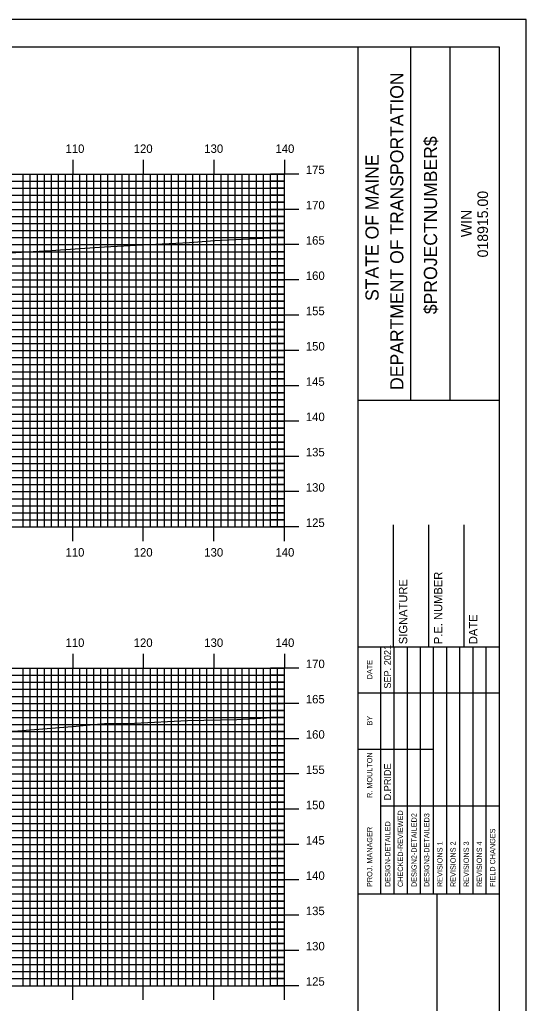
# Model space of a CAD drawing. Extents: x 1783041 to 1783384, y 442591 to 442811.
# Drawn here: x 1783309 to 1783380.7, y 442671.2 to 442810.5 of the extents above; entities that cross this region are included whole.
import ezdxf

# ---------------------------------------------------------------- set-up
doc = ezdxf.new("R2010")
doc.units = 0
for name, color, linetype in [('BORDER', 7, 'Continuous'), ('H_V ANNOTATION', 7, 'Continuous'), ('MAJOR', 7, 'Continuous'), ('MINOR', 7, 'Continuous'), ('PLOT BOUNDARY', 7, 'Continuous'), ('S_Roadway_Centerline', 7, 'Continuous')]:
    doc.layers.add(name, color=color, linetype=linetype)

msp = doc.modelspace()

# ---------------------------------------------------------------- linework, layer by layer
at = {"layer": 'BORDER'}
for p, q in [((1783356.86, 442596.67), (1783356.86, 442806.67)), ((1783364.32, 442756.66), (1783364.32, 442806.66)), ((1783369.91, 442756.66), (1783369.91, 442806.66)), ((1783356.86, 442756.65), (1783376.86, 442756.65)), ((1783356.86, 442756.65), (1783376.86, 442756.65)), ((1783361.86, 442721.67), (1783361.86, 442738.97)), ((1783361.86, 442721.67), (1783361.86, 442738.97)), ((1783366.86, 442721.67), (1783366.86, 442738.97)), ((1783366.86, 442721.67), (1783366.86, 442738.97)), ((1783371.86, 442721.67), (1783371.86, 442738.97)), ((1783371.86, 442721.67), (1783371.86, 442738.97)), ((1783356.86, 442721.67), (1783376.86, 442721.67)), ((1783356.86, 442721.67), (1783376.86, 442721.67)), ((1783356.86, 442686.67), (1783376.86, 442686.67)), ((1783356.86, 442686.67), (1783376.86, 442686.67)), ((1783368.04, 442616.67), (1783368.04, 442686.67)), ((1783368.04, 442616.67), (1783368.04, 442686.67))]:
    msp.add_line(p, q, dxfattribs=at)
msp.add_lwpolyline([(1783056.86, 442596.67), (1783376.86, 442596.67), (1783376.86, 442806.67), (1783056.86, 442806.67)], close=True, dxfattribs=at)
for points in [[(1783360.09, 442715.17), (1783360.09, 442721.67)], [(1783360.09, 442715.17), (1783360.09, 442721.67)], [(1783361.96, 442686.68), (1783361.96, 442721.67)], [(1783361.96, 442686.68), (1783361.96, 442721.67)], [(1783363.82, 442721.67), (1783363.82, 442686.68)], [(1783363.82, 442721.67), (1783363.82, 442686.68)], [(1783365.68, 442686.68), (1783365.68, 442721.67)], [(1783365.68, 442686.68), (1783365.68, 442721.67)], [(1783367.55, 442686.68), (1783367.55, 442721.67)], [(1783367.55, 442686.68), (1783367.55, 442721.67)], [(1783369.41, 442686.68), (1783369.41, 442721.67)], [(1783369.41, 442686.68), (1783369.41, 442721.67)], [(1783371.27, 442686.68), (1783371.27, 442721.67)], [(1783371.27, 442686.68), (1783371.27, 442721.67)], [(1783373.14, 442686.68), (1783373.14, 442721.67)], [(1783373.14, 442686.68), (1783373.14, 442721.67)], [(1783375, 442686.68), (1783375, 442721.67)], [(1783375, 442686.68), (1783375, 442721.67)], [(1783360.09, 442686.68), (1783360.09, 442720.26)], [(1783360.09, 442686.68), (1783360.09, 442720.26)], [(1783356.86, 442715.17), (1783376.86, 442715.17)], [(1783356.86, 442715.17), (1783376.86, 442715.17)], [(1783356.86, 442707.17), (1783360.09, 442707.17)], [(1783356.86, 442707.17), (1783360.09, 442707.17)], [(1783360.09, 442707.17), (1783367.54, 442707.17)], [(1783360.09, 442707.17), (1783367.54, 442707.17)], [(1783360.09, 442699.17), (1783376.86, 442699.17)], [(1783360.09, 442699.17), (1783376.86, 442699.17)]]:
    msp.add_lwpolyline(points, dxfattribs=at)
at = {"layer": 'MAJOR'}
for p, q in [((1783316.46, 442790.67), (1783316.46, 442788.67)), ((1783326.46, 442790.67), (1783326.46, 442788.67)), ((1783336.46, 442790.67), (1783336.46, 442788.67)), ((1783346.46, 442790.67), (1783346.46, 442788.67)), ((1783066.46, 442788.67), (1783346.46, 442788.67)), ((1783066.46, 442788.67), (1783346.46, 442788.67)), ((1783316.46, 442738.67), (1783316.46, 442788.67)), ((1783326.46, 442738.67), (1783326.46, 442788.67)), ((1783336.46, 442738.67), (1783336.46, 442788.67)), ((1783348.46, 442788.67), (1783344.46, 442788.67)), ((1783346.46, 442738.67), (1783346.46, 442788.67)), ((1783346.46, 442738.67), (1783346.46, 442788.67)), ((1783066.46, 442783.67), (1783346.46, 442783.67)), ((1783348.46, 442783.67), (1783344.46, 442783.67)), ((1783066.46, 442778.67), (1783346.46, 442778.67)), ((1783348.46, 442778.67), (1783344.46, 442778.67)), ((1783066.46, 442773.67), (1783346.46, 442773.67)), ((1783348.46, 442773.67), (1783344.46, 442773.67)), ((1783066.46, 442768.67), (1783346.46, 442768.67)), ((1783348.46, 442768.67), (1783344.46, 442768.67)), ((1783066.46, 442763.67), (1783346.46, 442763.67)), ((1783348.46, 442763.67), (1783344.46, 442763.67)), ((1783066.46, 442758.67), (1783346.46, 442758.67)), ((1783348.46, 442758.67), (1783344.46, 442758.67)), ((1783066.46, 442753.67), (1783346.46, 442753.67)), ((1783348.46, 442753.67), (1783344.46, 442753.67)), ((1783066.46, 442748.67), (1783346.46, 442748.67)), ((1783348.46, 442748.67), (1783344.46, 442748.67)), ((1783066.46, 442743.67), (1783346.46, 442743.67)), ((1783348.46, 442743.67), (1783344.46, 442743.67)), ((1783066.46, 442738.67), (1783346.46, 442738.67)), ((1783066.46, 442738.67), (1783346.46, 442738.67)), ((1783316.46, 442736.66), (1783316.46, 442738.67)), ((1783326.46, 442736.66), (1783326.46, 442738.67)), ((1783336.46, 442736.66), (1783336.46, 442738.67)), ((1783348.46, 442738.67), (1783344.46, 442738.67)), ((1783346.46, 442736.66), (1783346.46, 442738.67)), ((1783316.46, 442720.67), (1783316.46, 442718.67)), ((1783326.46, 442720.67), (1783326.46, 442718.67)), ((1783336.46, 442720.67), (1783336.46, 442718.67)), ((1783346.46, 442720.67), (1783346.46, 442718.67)), ((1783066.46, 442718.67), (1783346.46, 442718.67)), ((1783066.46, 442718.67), (1783346.46, 442718.67)), ((1783316.46, 442673.67), (1783316.46, 442718.67)), ((1783326.46, 442673.67), (1783326.46, 442718.67)), ((1783336.46, 442673.67), (1783336.46, 442718.67)), ((1783348.46, 442718.67), (1783344.46, 442718.67)), ((1783346.46, 442673.67), (1783346.46, 442718.67)), ((1783346.46, 442673.67), (1783346.46, 442718.67)), ((1783066.46, 442713.67), (1783346.46, 442713.67)), ((1783348.46, 442713.67), (1783344.46, 442713.67)), ((1783066.46, 442708.67), (1783346.46, 442708.67)), ((1783348.46, 442708.67), (1783344.46, 442708.67)), ((1783066.46, 442703.67), (1783346.46, 442703.67)), ((1783348.46, 442703.67), (1783344.46, 442703.67)), ((1783066.46, 442698.67), (1783346.46, 442698.67)), ((1783348.46, 442698.67), (1783344.46, 442698.67)), ((1783066.46, 442693.67), (1783346.46, 442693.67)), ((1783348.46, 442693.67), (1783344.46, 442693.67)), ((1783066.46, 442688.67), (1783346.46, 442688.67)), ((1783348.46, 442688.67), (1783344.46, 442688.67)), ((1783066.46, 442683.67), (1783346.46, 442683.67)), ((1783348.46, 442683.67), (1783344.46, 442683.67)), ((1783066.46, 442678.67), (1783346.46, 442678.67)), ((1783348.46, 442678.67), (1783344.46, 442678.67)), ((1783066.46, 442673.67), (1783346.46, 442673.67)), ((1783066.46, 442673.67), (1783346.46, 442673.67)), ((1783316.46, 442671.66), (1783316.46, 442673.67)), ((1783326.46, 442671.66), (1783326.46, 442673.67)), ((1783336.46, 442671.66), (1783336.46, 442673.67)), ((1783348.46, 442673.67), (1783344.46, 442673.67)), ((1783346.46, 442671.66), (1783346.46, 442673.67))]:
    msp.add_line(p, q, dxfattribs=at)
at = {"layer": 'MINOR'}
for p, q in [((1783309.46, 442738.67), (1783309.46, 442788.67)), ((1783310.46, 442738.67), (1783310.46, 442788.67)), ((1783311.46, 442738.67), (1783311.46, 442788.67)), ((1783312.46, 442738.67), (1783312.46, 442788.67)), ((1783313.46, 442738.67), (1783313.46, 442788.67)), ((1783314.46, 442738.67), (1783314.46, 442788.67)), ((1783315.46, 442738.67), (1783315.46, 442788.67)), ((1783317.46, 442738.67), (1783317.46, 442788.67)), ((1783318.46, 442738.67), (1783318.46, 442788.67)), ((1783319.46, 442738.67), (1783319.46, 442788.67)), ((1783320.46, 442738.67), (1783320.46, 442788.67)), ((1783321.46, 442738.67), (1783321.46, 442788.67)), ((1783322.46, 442738.67), (1783322.46, 442788.67)), ((1783323.46, 442738.67), (1783323.46, 442788.67)), ((1783324.46, 442738.67), (1783324.46, 442788.67)), ((1783325.46, 442738.67), (1783325.46, 442788.67)), ((1783327.46, 442738.67), (1783327.46, 442788.67)), ((1783328.46, 442738.67), (1783328.46, 442788.67)), ((1783329.46, 442738.67), (1783329.46, 442788.67)), ((1783330.46, 442738.67), (1783330.46, 442788.67)), ((1783331.46, 442738.67), (1783331.46, 442788.67)), ((1783332.46, 442738.67), (1783332.46, 442788.67)), ((1783333.46, 442738.67), (1783333.46, 442788.67)), ((1783334.46, 442738.67), (1783334.46, 442788.67)), ((1783335.46, 442738.67), (1783335.46, 442788.67)), ((1783337.46, 442738.67), (1783337.46, 442788.67)), ((1783338.46, 442738.67), (1783338.46, 442788.67)), ((1783339.46, 442738.67), (1783339.46, 442788.67)), ((1783340.46, 442738.67), (1783340.46, 442788.67)), ((1783341.46, 442738.67), (1783341.46, 442788.67)), ((1783342.46, 442738.67), (1783342.46, 442788.67)), ((1783343.46, 442738.67), (1783343.46, 442788.67)), ((1783344.46, 442738.67), (1783344.46, 442788.67)), ((1783345.46, 442738.67), (1783345.46, 442788.67)), ((1783066.46, 442787.67), (1783346.46, 442787.67)), ((1783346.46, 442787.67), (1783344.46, 442787.67)), ((1783066.46, 442786.67), (1783346.46, 442786.67)), ((1783066.46, 442785.67), (1783346.46, 442785.67)), ((1783346.46, 442786.67), (1783344.46, 442786.67)), ((1783346.46, 442785.67), (1783344.46, 442785.67)), ((1783066.46, 442784.67), (1783346.46, 442784.67)), ((1783346.46, 442784.67), (1783344.46, 442784.67)), ((1783066.46, 442782.67), (1783346.46, 442782.67)), ((1783346.46, 442782.67), (1783344.46, 442782.67)), ((1783066.46, 442781.67), (1783346.46, 442781.67)), ((1783346.46, 442781.67), (1783344.46, 442781.67)), ((1783066.46, 442780.67), (1783346.46, 442780.67)), ((1783346.46, 442780.67), (1783344.46, 442780.67)), ((1783066.46, 442779.67), (1783346.46, 442779.67)), ((1783346.46, 442779.67), (1783344.46, 442779.67)), ((1783066.46, 442777.67), (1783346.46, 442777.67)), ((1783346.46, 442777.67), (1783344.46, 442777.67)), ((1783066.46, 442776.67), (1783346.46, 442776.67)), ((1783066.46, 442775.67), (1783346.46, 442775.67)), ((1783346.46, 442776.67), (1783344.46, 442776.67)), ((1783346.46, 442775.67), (1783344.46, 442775.67)), ((1783066.46, 442774.67), (1783346.46, 442774.67)), ((1783346.46, 442774.67), (1783344.46, 442774.67)), ((1783066.46, 442772.67), (1783346.46, 442772.67)), ((1783066.46, 442771.67), (1783346.46, 442771.67)), ((1783346.46, 442772.67), (1783344.46, 442772.67)), ((1783346.46, 442771.67), (1783344.46, 442771.67)), ((1783066.46, 442770.67), (1783346.46, 442770.67)), ((1783346.46, 442770.67), (1783344.46, 442770.67)), ((1783066.46, 442769.67), (1783346.46, 442769.67)), ((1783346.46, 442769.67), (1783344.46, 442769.67)), ((1783066.46, 442767.67), (1783346.46, 442767.67)), ((1783346.46, 442767.67), (1783344.46, 442767.67)), ((1783066.46, 442766.67), (1783346.46, 442766.67)), ((1783346.46, 442766.67), (1783344.46, 442766.67)), ((1783066.46, 442765.67), (1783346.46, 442765.67)), ((1783066.46, 442764.67), (1783346.46, 442764.67)), ((1783346.46, 442765.67), (1783344.46, 442765.67)), ((1783346.46, 442764.67), (1783344.46, 442764.67)), ((1783066.46, 442762.67), (1783346.46, 442762.67)), ((1783066.46, 442761.67), (1783346.46, 442761.67)), ((1783346.46, 442762.67), (1783344.46, 442762.67)), ((1783346.46, 442761.67), (1783344.46, 442761.67)), ((1783066.46, 442760.67), (1783346.46, 442760.67)), ((1783346.46, 442760.67), (1783344.46, 442760.67)), ((1783066.46, 442759.67), (1783346.46, 442759.67)), ((1783346.46, 442759.67), (1783344.46, 442759.67)), ((1783066.46, 442757.67), (1783346.46, 442757.67)), ((1783346.46, 442757.67), (1783344.46, 442757.67)), ((1783066.46, 442756.67), (1783346.46, 442756.67)), ((1783346.46, 442756.67), (1783344.46, 442756.67)), ((1783066.46, 442755.67), (1783346.46, 442755.67)), ((1783066.46, 442754.67), (1783346.46, 442754.67)), ((1783346.46, 442755.67), (1783344.46, 442755.67)), ((1783346.46, 442754.67), (1783344.46, 442754.67)), ((1783066.46, 442752.67), (1783346.46, 442752.67)), ((1783346.46, 442752.67), (1783344.46, 442752.67)), ((1783066.46, 442751.67), (1783346.46, 442751.67)), ((1783066.46, 442750.67), (1783346.46, 442750.67)), ((1783346.46, 442751.67), (1783344.46, 442751.67)), ((1783346.46, 442750.67), (1783344.46, 442750.67)), ((1783066.46, 442749.67), (1783346.46, 442749.67)), ((1783346.46, 442749.67), (1783344.46, 442749.67)), ((1783066.46, 442747.67), (1783346.46, 442747.67)), ((1783346.46, 442747.67), (1783344.46, 442747.67)), ((1783066.46, 442746.67), (1783346.46, 442746.67)), ((1783346.46, 442746.67), (1783344.46, 442746.67)), ((1783066.46, 442745.67), (1783346.46, 442745.67)), ((1783346.46, 442745.67), (1783344.46, 442745.67)), ((1783066.46, 442744.67), (1783346.46, 442744.67)), ((1783346.46, 442744.67), (1783344.46, 442744.67)), ((1783066.46, 442742.67), (1783346.46, 442742.67)), ((1783346.46, 442742.67), (1783344.46, 442742.67)), ((1783066.46, 442741.67), (1783346.46, 442741.67)), ((1783346.46, 442741.67), (1783344.46, 442741.67)), ((1783066.46, 442740.67), (1783346.46, 442740.67)), ((1783066.46, 442739.67), (1783346.46, 442739.67)), ((1783346.46, 442740.67), (1783344.46, 442740.67)), ((1783346.46, 442739.67), (1783344.46, 442739.67)), ((1783309.46, 442673.67), (1783309.46, 442718.67)), ((1783310.46, 442673.67), (1783310.46, 442718.67)), ((1783311.46, 442673.67), (1783311.46, 442718.67)), ((1783312.46, 442673.67), (1783312.46, 442718.67)), ((1783313.46, 442673.67), (1783313.46, 442718.67)), ((1783314.46, 442673.67), (1783314.46, 442718.67)), ((1783315.46, 442673.67), (1783315.46, 442718.67)), ((1783317.46, 442673.67), (1783317.46, 442718.67)), ((1783318.46, 442673.67), (1783318.46, 442718.67)), ((1783319.46, 442673.67), (1783319.46, 442718.67)), ((1783320.46, 442673.67), (1783320.46, 442718.67)), ((1783321.46, 442673.67), (1783321.46, 442718.67)), ((1783322.46, 442673.67), (1783322.46, 442718.67)), ((1783323.46, 442673.67), (1783323.46, 442718.67)), ((1783324.46, 442673.67), (1783324.46, 442718.67)), ((1783325.46, 442673.67), (1783325.46, 442718.67)), ((1783327.46, 442673.67), (1783327.46, 442718.67)), ((1783328.46, 442673.67), (1783328.46, 442718.67)), ((1783329.46, 442673.67), (1783329.46, 442718.67)), ((1783330.46, 442673.67), (1783330.46, 442718.67)), ((1783331.46, 442673.67), (1783331.46, 442718.67)), ((1783332.46, 442673.67), (1783332.46, 442718.67)), ((1783333.46, 442673.67), (1783333.46, 442718.67)), ((1783334.46, 442673.67), (1783334.46, 442718.67)), ((1783335.46, 442673.67), (1783335.46, 442718.67)), ((1783337.46, 442673.67), (1783337.46, 442718.67)), ((1783338.46, 442673.67), (1783338.46, 442718.67)), ((1783339.46, 442673.67), (1783339.46, 442718.67)), ((1783340.46, 442673.67), (1783340.46, 442718.67)), ((1783341.46, 442673.67), (1783341.46, 442718.67)), ((1783342.46, 442673.67), (1783342.46, 442718.67)), ((1783343.46, 442673.67), (1783343.46, 442718.67)), ((1783344.46, 442673.67), (1783344.46, 442718.67)), ((1783345.46, 442673.67), (1783345.46, 442718.67)), ((1783066.46, 442717.67), (1783346.46, 442717.67)), ((1783346.46, 442717.67), (1783344.46, 442717.67)), ((1783066.46, 442716.67), (1783346.46, 442716.67)), ((1783066.46, 442715.67), (1783346.46, 442715.67)), ((1783346.46, 442716.67), (1783344.46, 442716.67)), ((1783346.46, 442715.67), (1783344.46, 442715.67)), ((1783066.46, 442714.67), (1783346.46, 442714.67)), ((1783346.46, 442714.67), (1783344.46, 442714.67)), ((1783066.46, 442712.67), (1783346.46, 442712.67)), ((1783066.46, 442711.67), (1783346.46, 442711.67)), ((1783346.46, 442712.67), (1783344.46, 442712.67)), ((1783346.46, 442711.67), (1783344.46, 442711.67)), ((1783066.46, 442710.67), (1783346.46, 442710.67)), ((1783346.46, 442710.67), (1783344.46, 442710.67)), ((1783066.46, 442709.67), (1783346.46, 442709.67)), ((1783346.46, 442709.67), (1783344.46, 442709.67)), ((1783066.46, 442707.67), (1783346.46, 442707.67)), ((1783346.46, 442707.67), (1783344.46, 442707.67)), ((1783066.46, 442706.67), (1783346.46, 442706.67)), ((1783346.46, 442706.67), (1783344.46, 442706.67)), ((1783066.46, 442705.67), (1783346.46, 442705.67)), ((1783066.46, 442704.67), (1783346.46, 442704.67)), ((1783346.46, 442705.67), (1783344.46, 442705.67)), ((1783346.46, 442704.67), (1783344.46, 442704.67)), ((1783066.46, 442702.67), (1783346.46, 442702.67)), ((1783066.46, 442701.67), (1783346.46, 442701.67)), ((1783346.46, 442702.67), (1783344.46, 442702.67)), ((1783346.46, 442701.67), (1783344.46, 442701.67)), ((1783066.46, 442700.67), (1783346.46, 442700.67)), ((1783346.46, 442700.67), (1783344.46, 442700.67)), ((1783066.46, 442699.67), (1783346.46, 442699.67)), ((1783346.46, 442699.67), (1783344.46, 442699.67)), ((1783066.46, 442697.67), (1783346.46, 442697.67)), ((1783346.46, 442697.67), (1783344.46, 442697.67)), ((1783066.46, 442696.67), (1783346.46, 442696.67)), ((1783346.46, 442696.67), (1783344.46, 442696.67)), ((1783066.46, 442695.67), (1783346.46, 442695.67)), ((1783346.46, 442695.67), (1783344.46, 442695.67)), ((1783066.46, 442694.67), (1783346.46, 442694.67)), ((1783346.46, 442694.67), (1783344.46, 442694.67)), ((1783066.46, 442692.67), (1783346.46, 442692.67)), ((1783346.46, 442692.67), (1783344.46, 442692.67)), ((1783066.46, 442691.67), (1783346.46, 442691.67)), ((1783066.46, 442690.67), (1783346.46, 442690.67)), ((1783346.46, 442691.67), (1783344.46, 442691.67)), ((1783346.46, 442690.67), (1783344.46, 442690.67)), ((1783066.46, 442689.67), (1783346.46, 442689.67)), ((1783346.46, 442689.67), (1783344.46, 442689.67)), ((1783066.46, 442687.67), (1783346.46, 442687.67)), ((1783066.46, 442686.67), (1783346.46, 442686.67)), ((1783346.46, 442687.67), (1783344.46, 442687.67)), ((1783346.46, 442686.67), (1783344.46, 442686.67)), ((1783066.46, 442685.67), (1783346.46, 442685.67)), ((1783346.46, 442685.67), (1783344.46, 442685.67)), ((1783066.46, 442684.67), (1783346.46, 442684.67)), ((1783346.46, 442684.67), (1783344.46, 442684.67)), ((1783066.46, 442682.67), (1783346.46, 442682.67)), ((1783346.46, 442682.67), (1783344.46, 442682.67)), ((1783066.46, 442681.67), (1783346.46, 442681.67)), ((1783346.46, 442681.67), (1783344.46, 442681.67)), ((1783066.46, 442680.67), (1783346.46, 442680.67)), ((1783066.46, 442679.67), (1783346.46, 442679.67)), ((1783346.46, 442680.67), (1783344.46, 442680.67)), ((1783346.46, 442679.67), (1783344.46, 442679.67)), ((1783066.46, 442677.67), (1783346.46, 442677.67)), ((1783066.46, 442676.67), (1783346.46, 442676.67)), ((1783346.46, 442677.67), (1783344.46, 442677.67)), ((1783346.46, 442676.67), (1783344.46, 442676.67)), ((1783066.46, 442675.67), (1783346.46, 442675.67)), ((1783346.46, 442675.67), (1783344.46, 442675.67)), ((1783066.46, 442674.67), (1783346.46, 442674.67)), ((1783346.46, 442674.67), (1783344.46, 442674.67))]:
    msp.add_line(p, q, dxfattribs=at)
at = {"layer": 'PLOT BOUNDARY'}
msp.add_lwpolyline([(1783040.67, 442590.55), (1783380.67, 442590.55), (1783380.67, 442810.55), (1783040.67, 442810.55)], close=True, dxfattribs=at)
at = {"layer": 'S_Roadway_Centerline'}
for points in [[(1783234.92, 442773.24), (1783241.03, 442773.57), (1783246.45, 442773.95), (1783258.82, 442775.16), (1783264.19, 442775.75), (1783269.01, 442775.81), (1783275.73, 442775.84), (1783282.77, 442776.15), (1783287.9, 442776.49), (1783292.39, 442776.6), (1783305.86, 442777.4), (1783313.39, 442777.82), (1783320.97, 442778.34), (1783329.14, 442778.77), (1783333, 442778.98), (1783336.56, 442779.24), (1783346.46, 442779.75)], [(1783230.35, 442704.87), (1783239.64, 442705.26), (1783247.37, 442705.76), (1783253.07, 442706.1), (1783270.57, 442707.7), (1783273.48, 442707.94), (1783276.7, 442708.27), (1783285.84, 442709.24), (1783293.59, 442709.9), (1783300.08, 442709.98), (1783308.14, 442709.72), (1783316.96, 442710.45), (1783320.97, 442710.8), (1783325.2, 442710.89), (1783332.73, 442711.24), (1783339.69, 442711.38), (1783346.46, 442711.78)]]:
    msp.add_lwpolyline(points, dxfattribs=at)

# ---------------------------------------------------------------- texts
at = {"layer": 'BORDER'}
for s, height, p in [('DEPARTMENT OF TRANSPORTATION', 1.8635, (1783363.27, 442758.08)), ('$PROJECTNUMBER$', 1.8635, (1783368.04, 442768.82)), ('$PROJECTNUMBER$', 1.8635, (1783368.04, 442768.82)), ('STATE OF MAINE', 1.8635, (1783359.77, 442770.69)), ('018915.00', 1.491, (1783375.25, 442776.86)), ('WIN', 1.491, (1783372.93, 442779.73)), ('WIN', 1.491, (1783372.93, 442779.73)), ('SIGNATURE', 1.181, (1783363.82, 442722.06)), ('SIGNATURE', 1.181, (1783363.82, 442722.06)), ('P.E. NUMBER', 1.1811, (1783368.78, 442722.06)), ('P.E. NUMBER', 1.1811, (1783368.78, 442722.06)), ('DATE', 1.181, (1783373.74, 442722.06)), ('DATE', 1.181, (1783373.74, 442722.06)), ('SEP. 2021', 0.969, (1783361.51, 442715.76)), ('DATE', 0.743, (1783358.87, 442717.08)), ('DATE', 0.743, (1783358.87, 442717.08)), ('BY', 0.743, (1783358.87, 442710.54)), ('BY', 0.743, (1783358.87, 442710.54)), ('R. MOULTON', 0.745, (1783358.87, 442700.28)), ('D.PRIDE', 0.969, (1783361.51, 442699.92)), ('CHECKED-REVIEWED', 0.7455, (1783363.22, 442687.65)), ('CHECKED-REVIEWED', 0.7455, (1783363.22, 442687.65)), ('DESIGN2-DETAILED2', 0.7455, (1783365.16, 442687.65)), ('DESIGN2-DETAILED2', 0.7455, (1783365.16, 442687.65)), ('DESIGN3-DETAILED3', 0.7455, (1783366.95, 442687.65)), ('DESIGN3-DETAILED3', 0.7455, (1783366.95, 442687.65)), ('DESIGN-DETAILED', 0.7455, (1783361.43, 442687.65)), ('DESIGN-DETAILED', 0.7455, (1783361.43, 442687.65)), ('PROJ. MANAGER', 0.7455, (1783358.87, 442687.65)), ('PROJ. MANAGER', 0.7455, (1783358.87, 442687.65)), ('FIELD CHANGES', 0.7455, (1783376.27, 442687.65)), ('FIELD CHANGES', 0.7455, (1783376.27, 442687.65)), ('REVISIONS 1', 0.7455, (1783368.81, 442687.65)), ('REVISIONS 1', 0.7455, (1783368.81, 442687.65)), ('REVISIONS 2', 0.7455, (1783370.68, 442687.65)), ('REVISIONS 2', 0.7455, (1783370.68, 442687.65)), ('REVISIONS 3', 0.7455, (1783372.54, 442687.65)), ('REVISIONS 3', 0.7455, (1783372.54, 442687.65)), ('REVISIONS 4', 0.7455, (1783374.4, 442687.65)), ('REVISIONS 4', 0.7455, (1783374.4, 442687.65))]:
    msp.add_text(s, height=height, rotation=90, dxfattribs=at).set_placement(p)
at = {"layer": 'H_V ANNOTATION'}
for s, p in [('110', (1783315.44, 442791.67)), ('120', (1783325.1, 442791.67)), ('130', (1783335.09, 442791.67)), ('140', (1783345.16, 442791.67)), ('175', (1783349.46, 442788.67)), ('170', (1783349.46, 442783.67)), ('165', (1783349.46, 442778.67)), ('160', (1783349.46, 442773.67)), ('155', (1783349.46, 442768.67)), ('150', (1783349.46, 442763.67)), ('145', (1783349.46, 442758.67)), ('140', (1783349.46, 442753.67)), ('135', (1783349.46, 442748.67)), ('130', (1783349.46, 442743.67)), ('125', (1783349.46, 442738.67)), ('110', (1783315.44, 442734.47)), ('120', (1783325.1, 442734.47)), ('130', (1783335.09, 442734.47)), ('140', (1783345.16, 442734.47)), ('110', (1783315.44, 442721.67)), ('120', (1783325.1, 442721.67)), ('130', (1783335.09, 442721.67)), ('140', (1783345.16, 442721.67)), ('170', (1783349.46, 442718.67)), ('165', (1783349.46, 442713.67)), ('160', (1783349.46, 442708.67)), ('155', (1783349.46, 442703.67)), ('150', (1783349.46, 442698.67)), ('145', (1783349.46, 442693.67)), ('140', (1783349.46, 442688.67)), ('135', (1783349.46, 442683.67)), ('130', (1783349.46, 442678.67)), ('125', (1783349.46, 442673.67))]:
    msp.add_text(s, height=1.2, dxfattribs=at).set_placement(p)

doc.saveas('drawing.dxf')
